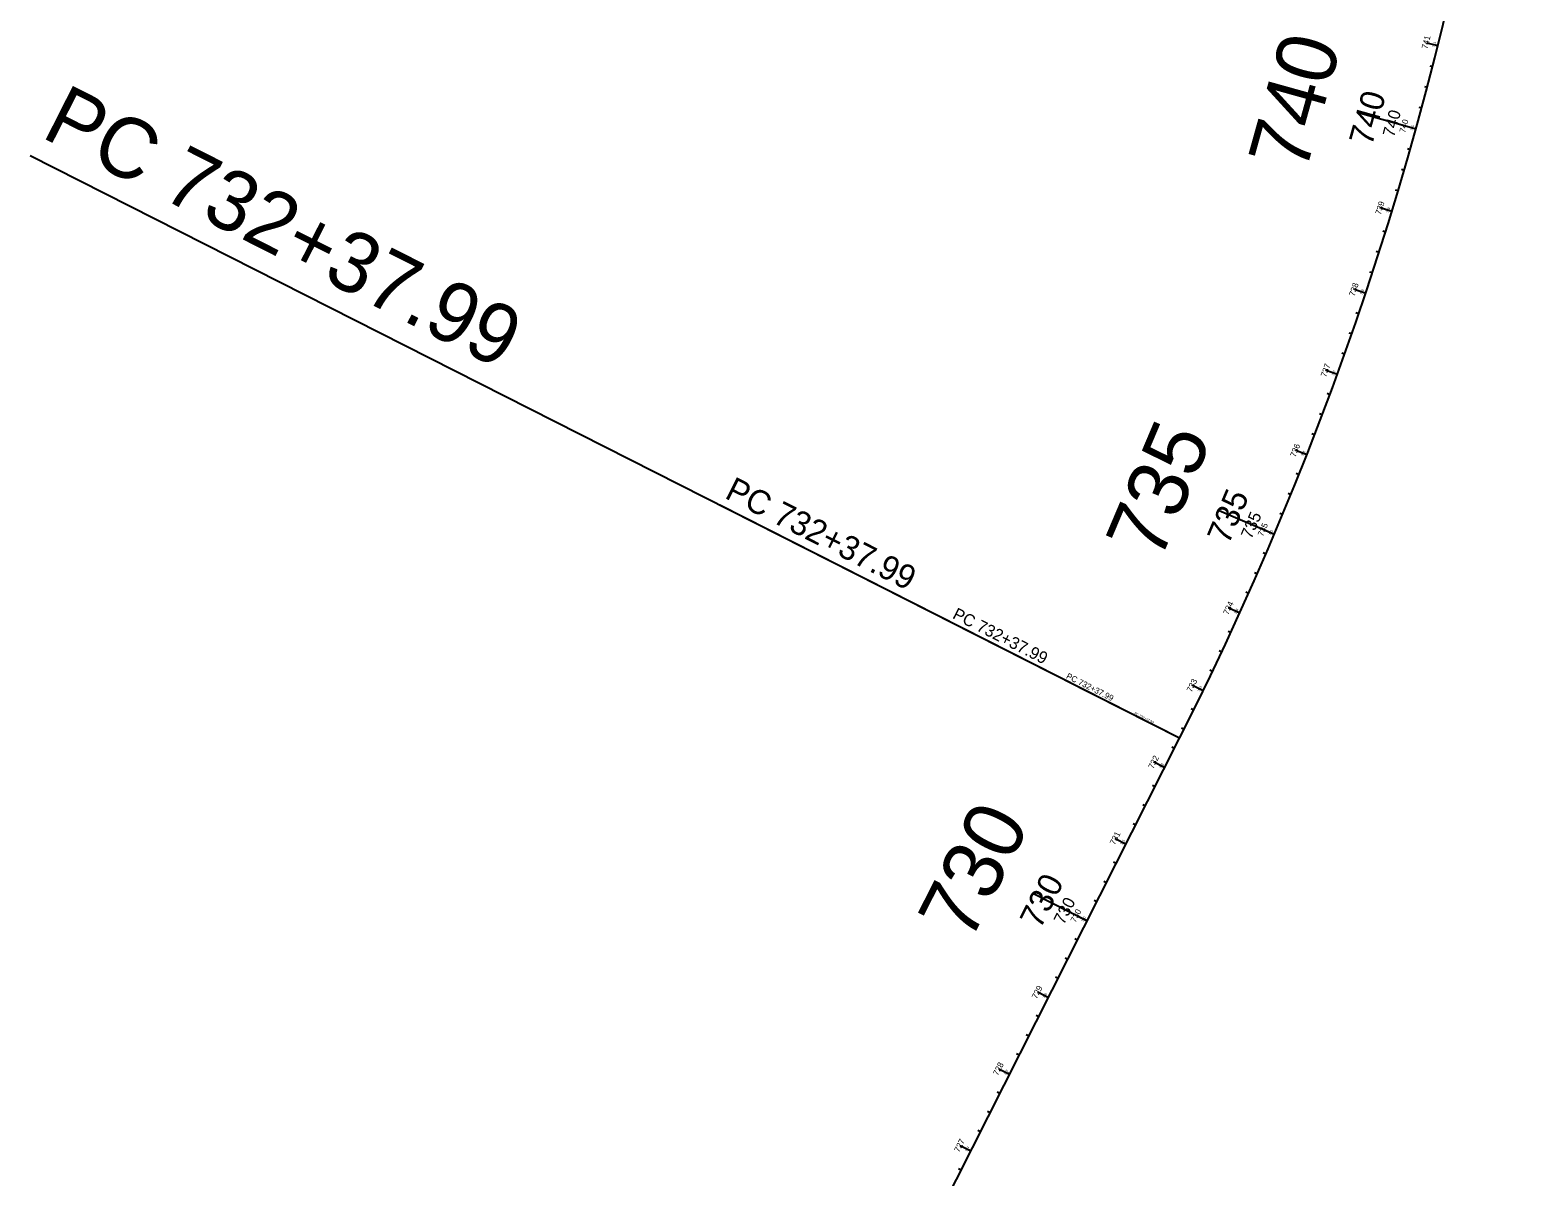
# Model space of a CAD drawing. Extents: x 353835 to 363333, y 126218 to 205387.
# Drawn here: x 354849 to 356604, y 194717 to 196051 of the extents above; entities that cross this region are included whole.
import ezdxf

# ---------------------------------------------------------------- set-up
doc = ezdxf.new("R2010")
doc.units = 0
for name, color, linetype in [('P_ALI_100_PIData', 7, 'Continuous'), ('P_ALI_100_Sta', 7, 'Continuous'), ('P_ALI_100_Tic', 7, 'Continuous'), ('P_ALI_20', 7, 'Continuous'), ('P_ALI_200_PIData', 7, 'Continuous'), ('P_ALI_200_Sta', 7, 'Continuous'), ('P_ALI_200_Tic', 7, 'Continuous'), ('P_ALI_20_PIData', 7, 'Continuous'), ('P_ALI_20_Sta', 7, 'Continuous'), ('P_ALI_20_Tic', 7, 'Continuous'), ('P_ALI_500_PIData', 7, 'Continuous'), ('P_ALI_500_Sta', 7, 'Continuous'), ('P_ALI_50_PIData', 7, 'Continuous'), ('P_ALI_50_Sta', 7, 'Continuous'), ('P_ALI_50_Tic', 7, 'Continuous')]:
    doc.layers.add(name, color=color, linetype=linetype)

msp = doc.modelspace()

# ---------------------------------------------------------------- linework, layer by layer
at = {"layer": 'P_ALI_100_PIData'}
for points in [[(356186.7, 195227.1), (355919, 195362.7)], [(356186.7, 195227.1), (356133.1, 195254.3)]]:
    msp.add_lwpolyline(points, dxfattribs=at)
at = {"layer": 'P_ALI_100_Tic'}
for points in [[(356480.8, 196034.7), (356487.6, 196033)], [(356394.5, 195955.2), (356462, 195936.4)], [(356448.5, 195940.1), (356462, 195936.4)], [(356427.2, 195842.5), (356433.9, 195840.4)], [(356396.7, 195747.4), (356403.3, 195745.2)], [(356363.8, 195653.2), (356370.3, 195650.8)], [(356328.4, 195559.8), (356334.9, 195557.3)], [(356232.6, 195492), (356297.1, 195464.7)], [(356284.2, 195470.2), (356297.1, 195464.7)], [(356250.5, 195376.1), (356256.8, 195373.2)], [(356208, 195285.8), (356214.2, 195282.7)], [(356163.3, 195196.4), (356169.5, 195193.3)], [(356118.1, 195107.2), (356124.3, 195104.1)], [(356016.7, 195046.5), (356079.1, 195014.8)], [(356066.7, 195021.2), (356079.1, 195014.8)], [(356027.7, 194928.8), (356034, 194925.6)], [(355982.5, 194839.6), (355988.8, 194836.4)], [(355937.3, 194750.4), (355943.6, 194747.2)]]:
    msp.add_lwpolyline(points, dxfattribs=at)
at = {"layer": 'P_ALI_20'}
msp.add_line((355558.1, 193986), (356186.7, 195227.1), dxfattribs=at)
msp.add_arc((352738.7, 196973.5), 3865, 333.1378, 11.3448, dxfattribs=at)
at = {"layer": 'P_ALI_200_PIData'}
msp.add_lwpolyline([(356186.7, 195227.1), (355651.4, 195498.3)], dxfattribs=at)
at = {"layer": 'P_ALI_200_Tic'}
for points in [[(356474, 196036.4), (356487.6, 196033)], [(356435, 195943.9), (356462, 195936.4)], [(356420.5, 195844.5), (356433.9, 195840.4)], [(356390.1, 195749.6), (356403.3, 195745.2)], [(356357.2, 195655.6), (356370.3, 195650.8)], [(356321.9, 195562.4), (356334.9, 195557.3)], [(356271.3, 195475.7), (356297.1, 195464.7)], [(356244.1, 195379), (356256.8, 195373.2)], [(356201.7, 195288.8), (356214.2, 195282.7)], [(356157, 195199.6), (356169.5, 195193.3)], [(356111.8, 195110.4), (356124.3, 195104.1)], [(356054.2, 195027.5), (356079.1, 195014.8)], [(356021.5, 194932), (356034, 194925.6)], [(355976.3, 194842.7), (355988.8, 194836.4)], [(355931.1, 194753.5), (355943.6, 194747.2)]]:
    msp.add_lwpolyline(points, dxfattribs=at)
at = {"layer": 'P_ALI_20_Tic'}
for points in [[(356484.8, 196033.7), (356487.6, 196033)], [(356480, 196009.2), (356481.4, 196008.8)], [(356473.7, 195985), (356475.1, 195984.6)], [(356467.2, 195960.8), (356468.6, 195960.5)], [(356459.3, 195937.1), (356462, 195936.4)], [(356453.8, 195912.7), (356455.2, 195912.3)], [(356446.9, 195888.7), (356448.2, 195888.3)], [(356439.8, 195864.7), (356441.1, 195864.3)], [(356431.2, 195841.2), (356433.9, 195840.4)], [(356425.1, 195816.9), (356426.5, 195816.5)], [(356417.6, 195793.1), (356418.9, 195792.7)], [(356409.9, 195769.3), (356411.2, 195768.9)], [(356400.7, 195746.1), (356403.3, 195745.2)], [(356394, 195722), (356395.3, 195721.5)], [(356385.8, 195698.3), (356387.1, 195697.9)], [(356377.5, 195674.8), (356378.8, 195674.3)], [(356367.7, 195651.7), (356370.3, 195650.8)], [(356360.4, 195627.8), (356361.7, 195627.3)], [(356351.6, 195604.4), (356352.9, 195603.9)], [(356342.7, 195581.1), (356344, 195580.6)], [(356332.3, 195558.3), (356334.9, 195557.3)], [(356324.4, 195534.6), (356325.7, 195534.1)], [(356315, 195511.4), (356316.3, 195510.9)], [(356305.4, 195488.3), (356306.7, 195487.8)], [(356294.5, 195465.8), (356297.1, 195464.7)], [(356285.9, 195442.3), (356287.2, 195441.7)], [(356276, 195419.4), (356277.2, 195418.8)], [(356265.8, 195396.5), (356267.1, 195396)], [(356254.3, 195374.3), (356256.8, 195373.2)], [(356245.1, 195351), (356246.4, 195350.4)], [(356234.6, 195328.4), (356235.8, 195327.8)], [(356223.9, 195305.8), (356225.1, 195305.2)], [(356211.7, 195283.9), (356214.2, 195282.7)], [(356202, 195260.9), (356203.2, 195260.2)], [(356190.8, 195238.5), (356192.1, 195237.9)], [(356179.6, 195216.2), (356180.8, 195215.6)], [(356167, 195194.5), (356169.5, 195193.3)], [(356157, 195171.6), (356158.2, 195171)], [(356145.7, 195149.3), (356146.9, 195148.7)], [(356134.4, 195127), (356135.6, 195126.4)], [(356121.8, 195105.3), (356124.3, 195104.1)], [(356111.8, 195082.4), (356113, 195081.7)], [(356100.5, 195060.1), (356101.7, 195059.4)], [(356089.2, 195037.8), (356090.4, 195037.1)], [(356076.6, 195016.1), (356079.1, 195014.8)], [(356066.6, 194993.2), (356067.8, 194992.5)], [(356055.3, 194970.9), (356056.5, 194970.2)], [(356044, 194948.6), (356045.3, 194947.9)], [(356031.5, 194926.9), (356034, 194925.6)], [(356021.4, 194904), (356022.7, 194903.3)], [(356010.1, 194881.7), (356011.4, 194881)], [(355998.8, 194859.4), (356000.1, 194858.7)], [(355986.3, 194837.7), (355988.8, 194836.4)], [(355976.2, 194814.8), (355977.5, 194814.1)], [(355964.9, 194792.5), (355966.2, 194791.8)], [(355953.6, 194770.1), (355954.9, 194769.5)], [(355941.1, 194748.5), (355943.6, 194747.2)], [(355931, 194725.5), (355932.3, 194724.9)]]:
    msp.add_lwpolyline(points, dxfattribs=at)
at = {"layer": 'P_ALI_500_PIData'}
msp.add_lwpolyline([(356186.7, 195227.1), (354848.5, 195904.9)], dxfattribs=at)
at = {"layer": 'P_ALI_50_PIData'}
msp.add_lwpolyline([(356186.7, 195227.1), (356052.9, 195294.9)], dxfattribs=at)
at = {"layer": 'P_ALI_50_Tic'}
for points in [[(356480.8, 196034.7), (356487.6, 196033)], [(356478, 196009.7), (356481.4, 196008.8)], [(356471.7, 195985.5), (356475.1, 195984.6)], [(356465.2, 195961.4), (356468.6, 195960.5)], [(356455.2, 195938.3), (356462, 195936.4)], [(356451.8, 195913.3), (356455.2, 195912.3)], [(356444.9, 195889.3), (356448.2, 195888.3)], [(356437.8, 195865.3), (356441.1, 195864.3)], [(356427.2, 195842.5), (356433.9, 195840.4)], [(356423.1, 195817.6), (356426.5, 195816.5)], [(356415.6, 195793.8), (356418.9, 195792.7)], [(356407.9, 195770), (356411.2, 195768.9)], [(356396.7, 195747.4), (356403.3, 195745.2)], [(356392, 195722.6), (356395.3, 195721.5)], [(356383.8, 195699), (356387.1, 195697.9)], [(356375.5, 195675.5), (356378.8, 195674.3)], [(356363.8, 195653.2), (356370.3, 195650.8)], [(356358.4, 195628.5), (356361.7, 195627.3)], [(356349.6, 195605.2), (356352.9, 195603.9)], [(356340.7, 195581.8), (356344, 195580.6)], [(356328.4, 195559.8), (356334.9, 195557.3)], [(356322.4, 195535.4), (356325.7, 195534.1)], [(356313, 195512.2), (356316.3, 195510.9)], [(356303.5, 195489.1), (356306.7, 195487.8)], [(356290.6, 195467.5), (356297.1, 195464.7)], [(356284, 195443.1), (356287.2, 195441.7)], [(356274, 195420.2), (356277.2, 195418.8)], [(356263.9, 195397.4), (356267.1, 195396)], [(356250.5, 195376.1), (356256.8, 195373.2)], [(356243.2, 195351.9), (356246.4, 195350.4)], [(356232.7, 195329.3), (356235.8, 195327.8)], [(356222, 195306.7), (356225.1, 195305.2)], [(356208, 195285.8), (356214.2, 195282.7)], [(356200.1, 195261.8), (356203.2, 195260.2)], [(356189, 195239.4), (356192.1, 195237.9)], [(356177.7, 195217.1), (356180.8, 195215.6)], [(356163.3, 195196.4), (356169.5, 195193.3)], [(356155.1, 195172.5), (356158.2, 195171)], [(356143.8, 195150.2), (356146.9, 195148.7)], [(356132.5, 195127.9), (356135.6, 195126.4)], [(356118.1, 195107.2), (356124.3, 195104.1)], [(356109.9, 195083.3), (356113, 195081.7)], [(356098.6, 195061), (356101.7, 195059.4)], [(356087.3, 195038.7), (356090.4, 195037.1)], [(356072.9, 195018), (356079.1, 195014.8)], [(356064.7, 194994.1), (356067.8, 194992.5)], [(356053.4, 194971.8), (356056.5, 194970.2)], [(356042.1, 194949.5), (356045.3, 194947.9)], [(356027.7, 194928.8), (356034, 194925.6)], [(356019.5, 194904.9), (356022.7, 194903.3)], [(356008.2, 194882.6), (356011.4, 194881)], [(355996.9, 194860.3), (356000.1, 194858.7)], [(355982.5, 194839.6), (355988.8, 194836.4)], [(355974.4, 194815.7), (355977.5, 194814.1)], [(355963.1, 194793.4), (355966.2, 194791.8)], [(355951.8, 194771.1), (355954.9, 194769.5)], [(355937.3, 194750.4), (355943.6, 194747.2)], [(355929.2, 194726.5), (355932.3, 194724.9)]]:
    msp.add_lwpolyline(points, dxfattribs=at)

# ---------------------------------------------------------------- texts
at = {"layer": 'P_ALI_100_PIData'}
msp.add_text('PC 732+37.99', height=14, rotation=333.1378, dxfattribs=at).set_placement((355921.3, 195367.2))
at = {"layer": 'P_ALI_100_Sta'}
for s, rotation, p in [('740', 74.434, (356436.2, 195925.8)), ('735', 67.0219, (356270.3, 195458.1)), ('730', 63.1378, (356051.8, 195009.5))]:
    msp.add_text(s, height=14, rotation=rotation, dxfattribs=at).set_placement(p)
at = {"layer": 'P_ALI_200_PIData'}
msp.add_text('PC 732+37.99', height=28, rotation=333.1378, dxfattribs=at).set_placement((355655.9, 195507.2))
at = {"layer": 'P_ALI_200_Sta'}
for s, rotation, p in [('740', 74.434, (356410.4, 195915.3)), ('735', 67.0219, (356243.6, 195451.5)), ('730', 63.1378, (356024.4, 195004.2))]:
    msp.add_text(s, height=28, rotation=rotation, dxfattribs=at).set_placement(p)
at = {"layer": 'P_ALI_20_PIData'}
msp.add_text('PC 732+37.99', height=2.8, rotation=333.1378, dxfattribs=at).set_placement((356133.6, 195255.2))
at = {"layer": 'P_ALI_20_Sta'}
for s, rotation, p in [('741', 75.9165, (356483.8, 196030.9)), ('740', 74.434, (356458.1, 195933.9)), ('739', 72.9516, (356430, 195838.1)), ('738', 71.4692, (356399.4, 195743)), ('737', 69.9868, (356366.3, 195648.7)), ('736', 68.5043, (356330.8, 195555.3)), ('735', 67.0219, (356292.9, 195462.9)), ('734', 65.5395, (356252.7, 195371.4)), ('733', 64.0571, (356210, 195281.1)), ('732', 63.1378, (356165.3, 195191.7)), ('731', 63.1378, (356120.2, 195102.8)), ('730', 63.1378, (356074.8, 195013.2)), ('729', 63.1378, (356029.7, 194924.1)), ('728', 63.1378, (355984.5, 194834.9)), ('727', 63.1378, (355939.3, 194745.7))]:
    msp.add_text(s, height=2.8, rotation=rotation, dxfattribs=at).set_placement(p)
at = {"layer": 'P_ALI_500_PIData'}
msp.add_text('PC 732+37.99', height=70, rotation=333.1378, dxfattribs=at).set_placement((354859.8, 195927.2))
at = {"layer": 'P_ALI_500_Sta'}
for s, rotation, p in [('740', 74.434, (356333.1, 195883.6)), ('735', 67.0219, (356163.5, 195431.5)), ('730', 63.1378, (355942.4, 194988.3))]:
    msp.add_text(s, height=70, rotation=rotation, dxfattribs=at).set_placement(p)
at = {"layer": 'P_ALI_50_PIData'}
msp.add_text('PC 732+37.99', height=7, rotation=333.1378, dxfattribs=at).set_placement((356054, 195297.2))
at = {"layer": 'P_ALI_50_Sta'}
for s, rotation, p in [('741', 75.9165, (356475.1, 196028.6)), ('740', 74.434, (356449.1, 195931.1)), ('739', 72.9516, (356420.9, 195835.7)), ('738', 71.4692, (356390.3, 195740.8)), ('737', 69.9868, (356357.2, 195646.8)), ('736', 68.5043, (356321.6, 195553.6)), ('735', 67.0219, (356283.7, 195461.4)), ('734', 65.5395, (356243.4, 195370.2)), ('733', 64.0571, (356200.7, 195280.1)), ('732', 63.1378, (356156, 195190.9)), ('731', 63.1378, (356111.2, 195102.4)), ('730', 63.1378, (356065.5, 195012.2)), ('729', 63.1378, (356020.4, 194923.2)), ('728', 63.1378, (355975.2, 194834)), ('727', 63.1378, (355930, 194744.8))]:
    msp.add_text(s, height=7, rotation=rotation, dxfattribs=at).set_placement(p)

doc.saveas('drawing.dxf')
